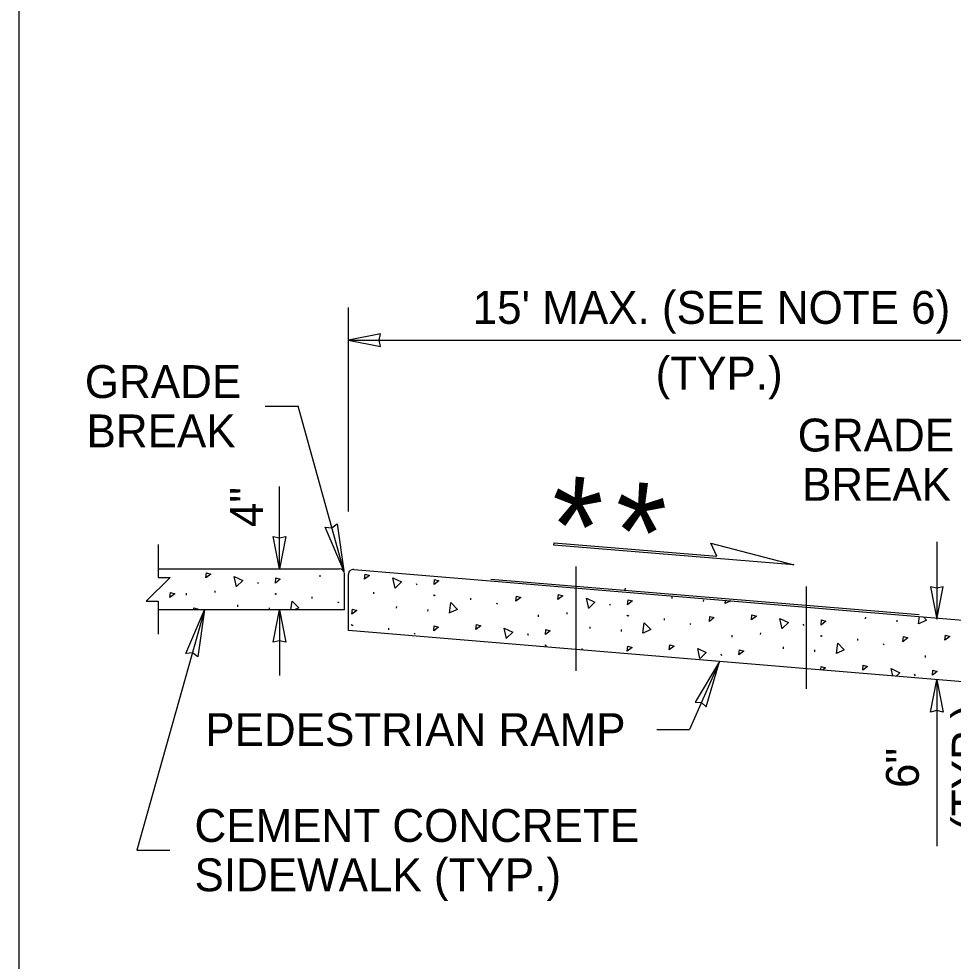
# Model space of a CAD drawing. Extents: x 99862 to 103151, y 100000 to 105076.
# Drawn here: x 99862 to 100316.6, y 100970.7 to 101429.3 of the extents above; entities that cross this region are included whole.
import ezdxf

# ---------------------------------------------------------------- set-up
doc = ezdxf.new("R2010")
doc.units = 0
for name, color, linetype in [('Level 1', 7, 'Continuous'), ('Level 13', 7, 'Continuous'), ('Level 15', 7, 'Continuous'), ('Level 20', 7, 'Continuous'), ('Level 26', 7, 'Continuous'), ('Level 5', 7, 'Continuous'), ('Level 6', 7, 'Continuous')]:
    doc.layers.add(name, color=color, linetype=linetype)

msp = doc.modelspace()

# ---------------------------------------------------------------- linework, layer by layer
at = {"layer": 'Level 1'}
msp.add_lwpolyline([(99862, 99999.5), (103151, 99999.5), (103151, 102075.5), (99862, 102075.5)], close=True, dxfattribs=at)
at = {"layer": 'Level 13'}
for p, q in [((100008.53, 101157.73), (100008.59, 101158.6)), ((100008.53, 101157.73), (100008.59, 101158.6)), ((99978.04, 101155.22), (99978.4, 101154.5)), ((99978.04, 101155.22), (99978.4, 101154.5)), ((100055.24, 101154.55), (100055.6, 101153.83)), ((100055.24, 101154.55), (100055.6, 101153.83)), ((99943.51, 101148.9), (99943.57, 101149.77)), ((99943.51, 101148.9), (99943.57, 101149.77)), ((99957.44, 101150.1), (99957.5, 101150.97)), ((99957.44, 101150.1), (99957.5, 101150.97)), ((99986.5, 101149.71), (99987.01, 101149.33)), ((99986.5, 101149.71), (99987.01, 101149.33)), ((99986.9, 101149.64), (99987.42, 101149.26)), ((99986.9, 101149.64), (99987.42, 101149.26)), ((100004.72, 101147.16), (100004.78, 101148.04)), ((100004.72, 101147.16), (100004.78, 101148.04)), ((100034.64, 101149.42), (100034.7, 101150.3)), ((100034.64, 101149.42), (100034.7, 101150.3)), ((100063.7, 101149.04), (100064.21, 101148.66)), ((100063.7, 101149.04), (100064.21, 101148.66)), ((100064.1, 101148.97), (100064.62, 101148.59)), ((100064.1, 101148.97), (100064.62, 101148.59)), ((100157.02, 101151.36), (100157.08, 101152.23)), ((100157.02, 101151.36), (100157.08, 101152.23)), ((100179.86, 101147.17), (100179.92, 101148.05)), ((100179.86, 101147.17), (100179.92, 101148.05)), ((99968.56, 101143.18), (99968.62, 101144.05)), ((99968.56, 101143.18), (99968.62, 101144.05)), ((100017.09, 101145.62), (100017.61, 101145.24)), ((100017.09, 101145.62), (100017.61, 101145.24)), ((100045.76, 101142.51), (100045.82, 101143.38)), ((100045.76, 101142.51), (100045.82, 101143.38)), ((100081.92, 101146.49), (100081.98, 101147.36)), ((100081.92, 101146.49), (100081.98, 101147.36)), ((100094.29, 101144.95), (100094.81, 101144.57)), ((100094.29, 101144.95), (100094.81, 101144.57)), ((100149.37, 101144.67), (100149.73, 101143.95)), ((100149.37, 101144.67), (100149.73, 101143.95)), ((100195.13, 101145.73), (100195.19, 101146.6)), ((100195.13, 101145.73), (100195.19, 101146.6)), ((99983.83, 101141.73), (99983.89, 101142.61)), ((99983.83, 101141.73), (99983.89, 101142.61)), ((100061.02, 101141.06), (100061.08, 101141.93)), ((100061.02, 101141.06), (100061.08, 101141.93)), ((100114.84, 101138.35), (100114.9, 101139.22)), ((100114.84, 101138.35), (100114.9, 101139.22)), ((100128.77, 101139.54), (100128.83, 101140.41)), ((100128.77, 101139.54), (100128.83, 101140.41)), ((100157.83, 101139.16), (100158.35, 101138.78)), ((100157.83, 101139.16), (100158.35, 101138.78)), ((100158.23, 101139.09), (100158.75, 101138.71)), ((100158.23, 101139.09), (100158.75, 101138.71)), ((100023.72, 101134.49), (100024.24, 101134.11)), ((100023.72, 101134.49), (100024.24, 101134.11)), ((100024.13, 101134.42), (100024.64, 101134.04)), ((100024.13, 101134.42), (100024.64, 101134.04)), ((100176.05, 101136.61), (100176.11, 101137.48)), ((100176.05, 101136.61), (100176.11, 101137.48)), ((100188.42, 101135.06), (100188.94, 101134.69)), ((100188.42, 101135.06), (100188.94, 101134.69)), ((100243.5, 101134.78), (100243.86, 101134.06)), ((100243.5, 101134.78), (100243.86, 101134.06)), ((100273.99, 101137.29), (100274.05, 101138.16)), ((100273.99, 101137.29), (100274.05, 101138.16)), ((100289.26, 101135.84), (100289.32, 101136.72)), ((100289.26, 101135.84), (100289.32, 101136.72)), ((100041.95, 101131.94), (100042.01, 101132.81)), ((100041.95, 101131.94), (100042.01, 101132.81)), ((100054.32, 101130.4), (100054.84, 101130.02)), ((100054.32, 101130.4), (100054.84, 101130.02)), ((100109.4, 101130.12), (100109.76, 101129.4)), ((100109.4, 101130.12), (100109.76, 101129.4)), ((100139.89, 101132.62), (100139.95, 101133.5)), ((100139.89, 101132.62), (100139.95, 101133.5)), ((100155.16, 101131.18), (100155.22, 101132.05)), ((100155.16, 101131.18), (100155.22, 101132.05)), ((100222.9, 101129.66), (100222.96, 101130.53)), ((100222.9, 101129.66), (100222.96, 101130.53)), ((100208.97, 101128.46), (100209.03, 101129.34)), ((100208.97, 101128.46), (100209.03, 101129.34)), ((100251.96, 101129.27), (100252.48, 101128.89)), ((100251.96, 101129.27), (100252.48, 101128.89)), ((100252.36, 101129.2), (100252.88, 101128.82)), ((100252.36, 101129.2), (100252.88, 101128.82)), ((100270.18, 101126.73), (100270.24, 101127.6)), ((100270.18, 101126.73), (100270.24, 101127.6)), ((100282.56, 101125.18), (100283.07, 101124.8)), ((100282.56, 101125.18), (100283.07, 101124.8)), ((100117.86, 101124.61), (100118.37, 101124.23)), ((100117.86, 101124.61), (100118.37, 101124.23)), ((100118.26, 101124.54), (100118.78, 101124.16)), ((100118.26, 101124.54), (100118.78, 101124.16)), ((100136.08, 101122.11), (100136.14, 101122.93)), ((100136.08, 101122.11), (100136.14, 101122.93)), ((100234.02, 101122.74), (100234.08, 101123.61)), ((100234.02, 101122.74), (100234.08, 101123.61)), ((100249.29, 101121.29), (100249.35, 101122.17)), ((100249.29, 101121.29), (100249.35, 101122.17)), ((100203.53, 101120.23), (100203.89, 101119.51)), ((100203.53, 101120.23), (100203.89, 101119.51)), ((100303.11, 101118.58), (100303.17, 101119.45)), ((100303.11, 101118.58), (100303.17, 101119.45)), ((100297.66, 101110.35), (100298.02, 101109.63)), ((100297.66, 101110.35), (100298.02, 101109.63))]:
    msp.add_line(p, q, dxfattribs=at)
for points in [[(99929.82, 101173.47), (99929.82, 101157.47), (99935.63, 101157.47), (99924.01, 101145.86), (99929.82, 101145.86), (99929.82, 101129.86)], [(99929.82, 101173.47), (99929.82, 101157.47), (99935.63, 101157.47), (99924.01, 101145.86), (99929.82, 101145.86), (99929.82, 101129.86)], [(99952.98, 101157.22), (99953.22, 101159.67), (99955.34, 101159.02), (99952.98, 101157.22)], [(99952.98, 101157.22), (99953.22, 101159.67), (99955.34, 101159.02), (99952.98, 101157.22)], [(99967.91, 101152.93), (99966.83, 101157.94), (99970.94, 101155.94), (99967.97, 101152.98)], [(99967.91, 101152.93), (99966.83, 101157.94), (99970.94, 101155.94), (99967.97, 101152.98)], [(99986.84, 101154.75), (99987.08, 101157.2), (99989.21, 101156.56), (99986.84, 101154.75)], [(99986.84, 101154.75), (99987.08, 101157.2), (99989.21, 101156.56), (99986.84, 101154.75)], [(100030.18, 101156.54), (100030.42, 101158.99), (100032.54, 101158.35), (100030.18, 101156.54)], [(100030.18, 101156.54), (100030.42, 101158.99), (100032.54, 101158.35), (100030.18, 101156.54)], [(100045.11, 101152.25), (100044.03, 101157.26), (100048.14, 101155.27), (100045.17, 101152.31)], [(100045.11, 101152.25), (100044.03, 101157.26), (100048.14, 101155.27), (100045.17, 101152.31)], [(100064.04, 101154.08), (100064.28, 101156.53), (100066.4, 101155.88), (100064.04, 101154.08)], [(100064.04, 101154.08), (100064.28, 101156.53), (100066.4, 101155.88), (100064.04, 101154.08)], [(99935.47, 101147.65), (99935.71, 101150.1), (99937.84, 101149.46), (99935.47, 101147.65)], [(99935.47, 101147.65), (99935.71, 101150.1), (99937.84, 101149.46), (99935.47, 101147.65)], [(100103.84, 101145.97), (100104.09, 101148.42), (100106.21, 101147.77), (100103.84, 101145.97)], [(100103.84, 101145.97), (100104.09, 101148.42), (100106.21, 101147.77), (100103.84, 101145.97)], [(100124.31, 101146.66), (100124.55, 101149.11), (100126.67, 101148.47), (100124.31, 101146.66)], [(100124.31, 101146.66), (100124.55, 101149.11), (100126.67, 101148.47), (100124.31, 101146.66)], [(99994.39, 101141.67), (99994.98, 101145.89), (99998.16, 101142.6), (99996.14, 101141.67)], [(99994.39, 101141.67), (99994.98, 101145.89), (99998.16, 101142.6), (99996.14, 101141.67)], [(100071.47, 101140.14), (100072.18, 101145.21), (100075.36, 101141.93), (100071.56, 101140.17)], [(100071.47, 101140.14), (100072.18, 101145.21), (100075.36, 101141.93), (100071.56, 101140.17)], [(100139.24, 101142.37), (100138.16, 101147.38), (100142.27, 101145.38), (100139.3, 101142.43)], [(100139.24, 101142.37), (100138.16, 101147.38), (100142.27, 101145.38), (100139.3, 101142.43)], [(100158.17, 101144.19), (100158.41, 101146.64), (100160.54, 101146), (100158.17, 101144.19)], [(100158.17, 101144.19), (100158.41, 101146.64), (100160.54, 101146), (100158.17, 101144.19)], [(100205.58, 101144.8), (100205.78, 101146.3)], [(100205.58, 101144.8), (100205.78, 101146.3)], [(100208.36, 101146.09), (100205.66, 101144.83)], [(100208.36, 101146.09), (100205.66, 101144.83)], [(99947.01, 101141.67), (99947.11, 101142.65), (99949.23, 101142.01), (99948.79, 101141.67)], [(99947.01, 101141.67), (99947.11, 101142.65), (99949.23, 101142.01), (99948.79, 101141.67)], [(100024.07, 101139.53), (100024.31, 101141.98), (100026.43, 101141.33), (100024.07, 101139.53)], [(100024.07, 101139.53), (100024.31, 101141.98), (100026.43, 101141.33), (100024.07, 101139.53)], [(100218.44, 101136.78), (100218.68, 101139.23), (100220.81, 101138.58), (100218.44, 101136.78)], [(100218.44, 101136.78), (100218.68, 101139.23), (100220.81, 101138.58), (100218.44, 101136.78)], [(100084.34, 101132.11), (100084.58, 101134.56), (100086.7, 101133.92), (100084.34, 101132.11)], [(100084.34, 101132.11), (100084.58, 101134.56), (100086.7, 101133.92), (100084.34, 101132.11)], [(100165.61, 101130.26), (100166.31, 101135.33), (100169.49, 101132.05), (100165.69, 101130.29)], [(100165.61, 101130.26), (100166.31, 101135.33), (100169.49, 101132.05), (100165.69, 101130.29)], [(100197.98, 101136.08), (100198.22, 101138.53), (100200.34, 101137.89), (100197.98, 101136.08)], [(100197.98, 101136.08), (100198.22, 101138.53), (100200.34, 101137.89), (100197.98, 101136.08)], [(100233.37, 101132.49), (100232.29, 101137.5), (100236.41, 101135.5), (100233.44, 101132.55)], [(100233.37, 101132.49), (100232.29, 101137.5), (100236.41, 101135.5), (100233.44, 101132.55)], [(100252.3, 101134.31), (100252.54, 101136.76), (100254.67, 101136.12), (100252.3, 101134.31)], [(100252.3, 101134.31), (100252.54, 101136.76), (100254.67, 101136.12), (100252.3, 101134.31)], [(100299.71, 101134.92), (100300.2, 101138.43)], [(100299.71, 101134.92), (100300.2, 101138.43)], [(100302.08, 101138.27), (100303.59, 101136.71), (100299.79, 101134.95)], [(100302.08, 101138.27), (100303.59, 101136.71), (100299.79, 101134.95)], [(100063.87, 101131.42), (100064.11, 101133.87), (100066.24, 101133.22), (100063.87, 101131.42)], [(100063.87, 101131.42), (100064.11, 101133.87), (100066.24, 101133.22), (100063.87, 101131.42)], [(100099.26, 101127.82), (100098.19, 101132.83), (100102.3, 101130.84), (100099.33, 101127.88)], [(100099.26, 101127.82), (100098.19, 101132.83), (100102.3, 101130.84), (100099.33, 101127.88)], [(100118.2, 101129.64), (100118.44, 101132.1), (100120.56, 101131.45), (100118.2, 101129.64)], [(100118.2, 101129.64), (100118.44, 101132.1), (100120.56, 101131.45), (100118.2, 101129.64)], [(100259.74, 101120.37), (100260.44, 101125.45), (100263.62, 101122.16), (100259.82, 101120.4)], [(100259.74, 101120.37), (100260.44, 101125.45), (100263.62, 101122.16), (100259.82, 101120.4)], [(100292.11, 101126.2), (100292.35, 101128.65), (100294.47, 101128.01), (100292.11, 101126.2)], [(100292.11, 101126.2), (100292.35, 101128.65), (100294.47, 101128.01), (100292.11, 101126.2)], [(100312.57, 101126.89), (100312.81, 101129.35), (100314.94, 101128.7), (100312.57, 101126.89)], [(100312.57, 101126.89), (100312.81, 101129.35), (100314.94, 101128.7), (100312.57, 101126.89)], [(100158, 101121.54), (100158.25, 101123.99), (100160.37, 101123.34), (100158, 101121.54)], [(100158, 101121.54), (100158.25, 101123.99), (100160.37, 101123.34), (100158, 101121.54)], [(100178.47, 101122.23), (100178.71, 101124.68), (100180.83, 101124.03), (100178.47, 101122.23)], [(100178.47, 101122.23), (100178.71, 101124.68), (100180.83, 101124.03), (100178.47, 101122.23)], [(100193.4, 101117.94), (100192.32, 101122.95), (100196.43, 101120.95), (100193.46, 101118)], [(100193.4, 101117.94), (100192.32, 101122.95), (100196.43, 101120.95), (100193.46, 101118)], [(100212.33, 101119.76), (100212.57, 101122.21), (100214.7, 101121.57), (100212.33, 101119.76)], [(100212.33, 101119.76), (100212.57, 101122.21), (100214.7, 101121.57), (100212.33, 101119.76)], [(100252.21, 101112.43), (100252.38, 101114.1), (100254.5, 101113.46), (100253.06, 101112.36)], [(100252.21, 101112.43), (100252.38, 101114.1), (100254.5, 101113.46), (100253.06, 101112.36)], [(100272.6, 101112.35), (100272.84, 101114.8), (100274.97, 101114.15), (100272.6, 101112.35)], [(100272.6, 101112.35), (100272.84, 101114.8), (100274.97, 101114.15), (100272.6, 101112.35)], [(100287.22, 101109.51), (100286.45, 101113.07), (100290.57, 101111.07), (100288.86, 101109.38)], [(100287.22, 101109.51), (100286.45, 101113.07), (100290.57, 101111.07), (100288.86, 101109.38)], [(100306.46, 101109.88), (100306.7, 101112.33), (100308.83, 101111.69), (100306.46, 101109.88)], [(100306.46, 101109.88), (100306.7, 101112.33), (100308.83, 101111.69), (100306.46, 101109.88)]]:
    msp.add_lwpolyline(points, dxfattribs=at)
at = {"layer": 'Level 15'}
for p, q in [((100022.31, 101189.58), (100022.31, 101288.87)), ((100022.31, 101189.58), (100022.31, 101288.87)), ((100022.31, 101272.87), (100382.31, 101272.87)), ((100022.31, 101272.87), (100382.31, 101272.87)), ((99981.84, 101240.77), (99997.84, 101240.77)), ((99981.84, 101240.77), (99997.84, 101240.77)), ((100020.08, 101160.68), (99997.84, 101240.77)), ((100020.08, 101160.68), (99997.84, 101240.77)), ((99988.74, 101161.67), (99988.74, 101201.67)), ((99988.74, 101161.67), (99988.74, 101201.67)), ((100308.59, 101174.82), (100308.59, 101137.74)), ((99952.32, 101141.67), (99919.45, 101024.74)), ((99988.74, 101141.67), (99988.74, 101109.67)), ((100202.9, 101116.52), (100188.37, 101083.4)), ((100308.59, 101107.73), (100308.59, 101026.67)), ((100172.37, 101083.4), (100188.37, 101083.4)), ((99919.45, 101024.74), (99935.45, 101024.74))]:
    msp.add_line(p, q, dxfattribs=at)
for points in [[(100022.31, 101272.87), (100038.03, 101269.79), (100037.3, 101272.87), (100038.03, 101275.95)], [(100022.31, 101272.87), (100038.03, 101269.79), (100037.3, 101272.87), (100038.03, 101275.95)], [(100020.08, 101160.68), (100011.1, 101181.88), (100014.26, 101181.66), (100016.85, 101183.48)], [(100020.08, 101160.68), (100011.1, 101181.88), (100014.26, 101181.66), (100016.85, 101183.48)], [(99988.74, 101161.67), (99985.66, 101177.39), (99988.74, 101176.66), (99991.83, 101177.39)], [(99988.74, 101161.67), (99985.66, 101177.39), (99988.74, 101176.66), (99991.83, 101177.39)], [(100308.59, 101137.21), (100311.67, 101152.94), (100308.59, 101152.21), (100305.51, 101152.93)], [(99952.32, 101141.67), (99949.01, 101118.88), (99946.43, 101120.71), (99943.27, 101120.5)], [(99988.74, 101141.67), (99991.83, 101125.94), (99988.74, 101126.67), (99985.66, 101125.94)], [(99988.74, 101141.67), (99991.83, 101125.94), (99988.74, 101126.67), (99985.66, 101125.94)], [(100202.9, 101116.52), (100191, 101096.82), (100194.16, 101096.59), (100196.46, 101094.42)], [(100308.59, 101107.69), (100311.67, 101091.96), (100308.59, 101092.69), (100305.51, 101091.97)]]:
    msp.add_lwpolyline(points, close=True, dxfattribs=at)
at = {"layer": 'Level 20'}
msp.add_lwpolyline([(100122.37, 101174.27), (100201.65, 101167.86), (100198.64, 101174.22), (100239.13, 101163.66), (100122.28, 101173.11)], close=True, dxfattribs=at)
at = {"layer": 'Level 26'}
for p, q in [((99929.82, 101161.67), (100017.93, 101161.67)), ((99929.82, 101161.67), (100017.93, 101161.67)), ((100020.43, 101141.67), (100020.43, 101159.17)), ((100020.43, 101141.67), (100020.43, 101159.17)), ((100022.31, 101131.59), (100022.31, 101158.87)), ((100022.31, 101131.59), (100022.31, 101158.87)), ((100025.01, 101161.36), (100378.14, 101131.94)), ((100025.01, 101161.36), (100378.14, 101131.94)), ((100020.43, 101141.67), (99929.82, 101141.67)), ((100020.43, 101141.67), (99929.82, 101141.67)), ((100381.37, 101101.67), (100022.31, 101131.59)), ((100381.37, 101101.67), (100022.31, 101131.59))]:
    msp.add_line(p, q, dxfattribs=at)
for centre, start, end in [((100017.93, 101159.17), 0, 90), ((100017.93, 101159.17), 0, 90), ((100024.81, 101158.87), 85.2364, 180), ((100024.81, 101158.87), 85.2364, 180)]:
    msp.add_arc(centre, 2.5, start, end, dxfattribs=at)
at = {"layer": 'Level 5'}
for p, q in [((100132.98, 101162.84), (100132.98, 101112.01)), ((100244.98, 101153.1), (100244.98, 101103.27))]:
    msp.add_line(p, q, dxfattribs=at)
at = {"layer": 'Level 6'}
msp.add_line((100091.61, 101156.56), (100300.11, 101139.37), dxfattribs=at)

# ---------------------------------------------------------------- texts
at = {"layer": 'Level 20'}
for s, p in [("15' MAX. (SEE NOTE 6)", (100082.8, 101280.87)), ('(TYP.)', (100171.82, 101248.87)), ('GRADE', (100240.93, 101218.75)), ('BREAK', (100243.03, 101194.75)), ('CEMENT CONCRETE', (99947.46, 101028.75)), ('SIDEWALK (TYP.)', (99947.46, 101004.75))]:
    msp.add_text(s, height=16, dxfattribs=at).set_placement(p)
for s, height, rotation, p in [('GRADE', 16, 360, (99894.11, 101244.77)), (' BREAK', 16, 360, (99888.98, 101220.77)), ('*', 48, 354.8067, (100118.16, 101159.68)), ('*', 48, 354.8067, (100149.11, 101156.86)), ('4"', 16, 90, (99980.76, 101181.96)), ('(TYP.)', 16, 89.8793, (100331.82, 101034.08)), ('PEDESTRIAN RAMP', 16, 360, (99952.69, 101075.4)), ('6"', 16, 89.8793, (100299.87, 101054.97))]:
    msp.add_text(s, height=height, rotation=rotation, dxfattribs=at).set_placement(p)

doc.saveas('drawing.dxf')
